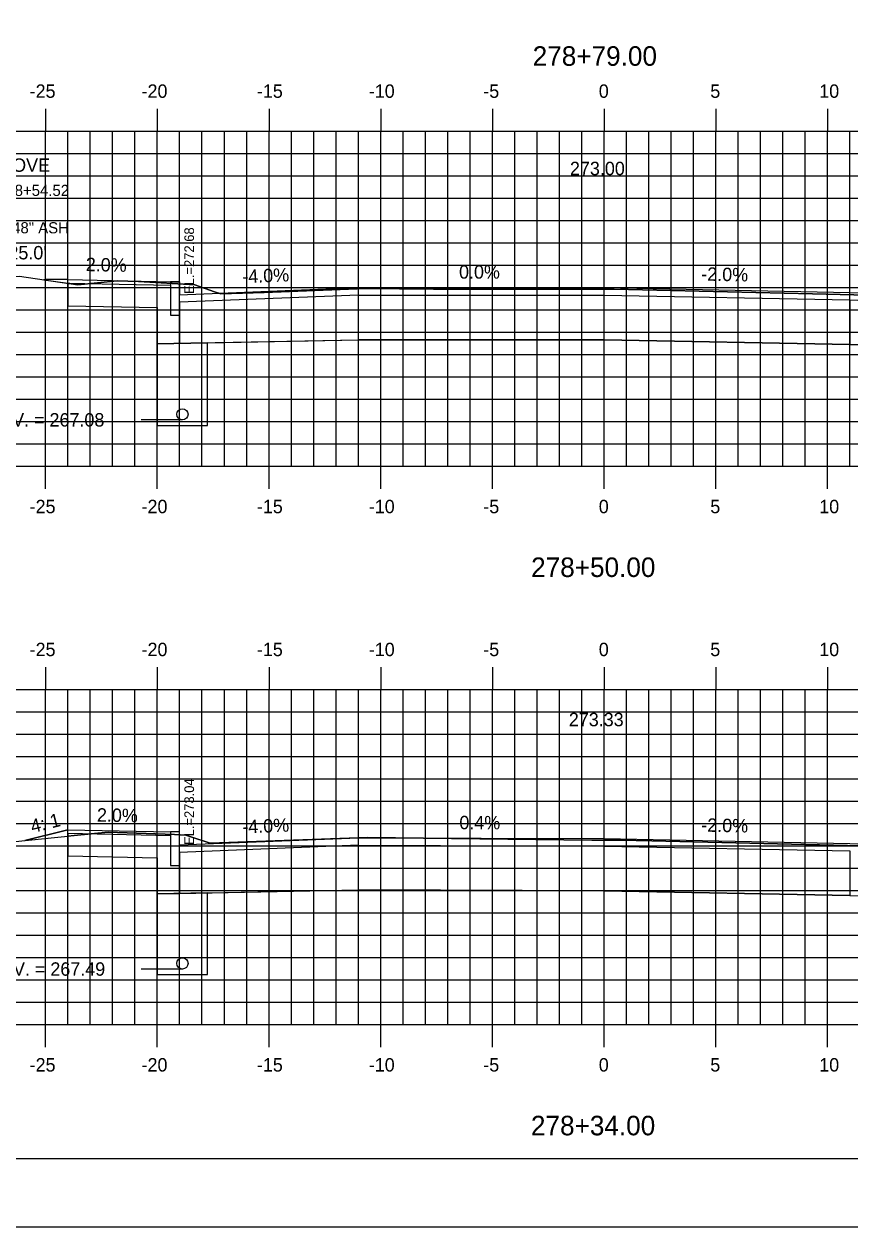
# Model space of a CAD drawing. Extents: x 854676 to 854846, y 366268 to 366378.
# Drawn here: x 854733.1 to 854770.1, y 366268.2 to 366322 of the extents above; entities that cross this region are included whole.
import ezdxf

# ---------------------------------------------------------------- set-up
doc = ezdxf.new("R2010")
doc.units = 0
for name, color, linetype in [('ANNOTATION', 7, 'Continuous'), ('BORDER', 7, 'Continuous'), ('D_Curb_Type_1_Lt', 7, 'Continuous'), ('D_Roadway_Centerline', 7, 'Continuous'), ('D_Roadway_Centerline_Text', 7, 'Continuous'), ('D_Roadway_Edge_Shoulder', 7, 'Continuous'), ('D_Roadway_FinishedGrade', 7, 'Continuous'), ('D_Roadway_Sidewalks_Paved', 7, 'Continuous'), ('D_Roadway_SubGrade', 7, 'Continuous'), ('D_Text_Monospaced', 7, 'Continuous'), ('D_Text_Standard', 7, 'Continuous'), ('H_V ANNOTATION', 7, 'Continuous'), ('JUNK COM EXC', 7, 'Continuous'), ('JUNK FILL', 7, 'Continuous'), ('junk strct exc', 7, 'Continuous'), ('MAJOR', 7, 'Continuous'), ('MINOR', 7, 'Continuous'), ('PDRAIN', 7, 'Continuous'), ('PLOT BOUNDARY', 7, 'Continuous'), ('S_Roadway_Centerline', 7, 'Continuous')]:
    doc.layers.add(name, color=color, linetype=linetype)

msp = doc.modelspace()

# ---------------------------------------------------------------- linework, layer by layer
at = {"layer": 'BORDER'}
msp.add_line((854684.107, 366271.236), (854844.107, 366271.236), dxfattribs=at)
at = {"layer": 'D_Curb_Type_1_Lt'}
for points in [[(854739.69, 366310.503), (854739.69, 366309.003), (854740.106, 366309.003), (854740.106, 366310.503)], [(854739.69, 366285.864), (854739.69, 366284.364), (854740.106, 366284.364), (854740.106, 366285.864)]]:
    msp.add_lwpolyline(points, close=True, dxfattribs=at)
at = {"layer": 'D_Roadway_Centerline'}
for points in [[(854734.024, 366310.589), (854734.101, 366310.615), (854735.101, 366310.595), (854739.69, 366310.503), (854740.101, 366310.503), (854740.106, 366309.92), (854748.106, 366310.24)], [(854748.106, 366310.24), (854759.106, 366310.24), (854770.106, 366310.02)]]:
    msp.add_lwpolyline(points, dxfattribs=at)
at = {"layer": 'D_Roadway_Edge_Shoulder'}
for points in [[(854740.106, 366309.92), (854748.106, 366310.24), (854759.106, 366310.24), (854770.106, 366310.02), (854778.103, 366309.701)], [(854740.106, 366285.281), (854748.106, 366285.601), (854759.106, 366285.566), (854770.106, 366285.346), (854778.107, 366285.025)]]:
    msp.add_lwpolyline(points, dxfattribs=at)
at = {"layer": 'D_Roadway_FinishedGrade'}
msp.add_line((854733.178, 366285.475), (854735.101, 366285.956), dxfattribs=at)
for points in [[(854734.101, 366310.615), (854734.024, 366310.589)], [(854735.101, 366310.595), (854734.101, 366310.615)]]:
    msp.add_lwpolyline(points, dxfattribs=at)
at = {"layer": 'D_Roadway_Sidewalks_Paved'}
for points in [[(854735.101, 366310.595), (854739.69, 366310.503), (854739.69, 366310.337), (854735.101, 366310.429)], [(854735.101, 366285.956), (854739.69, 366285.864), (854739.69, 366285.697), (854735.101, 366285.789)]]:
    msp.add_lwpolyline(points, close=True, dxfattribs=at)
at = {"layer": 'D_Roadway_SubGrade'}
for points in [[(854735.101, 366310.429), (854735.101, 366309.428), (854739.106, 366309.348), (854739.106, 366307.727), (854740.106, 366307.747)], [(854735.101, 366285.789), (854735.101, 366284.789), (854739.106, 366284.709), (854739.106, 366283.087), (854740.106, 366283.107)]]:
    msp.add_lwpolyline(points, dxfattribs=at)
for points in [[(854748.106, 366309.907), (854740.106, 366309.587), (854740.106, 366307.747), (854748.106, 366307.907)], [(854748.106, 366307.907), (854748.106, 366309.907), (854759.106, 366309.907), (854770.106, 366309.687), (854770.106, 366307.687), (854759.106, 366307.907)], [(854770.106, 366309.687), (854778.106, 366309.367), (854778.106, 366307.527), (854770.106, 366307.687)], [(854748.106, 366285.267), (854740.106, 366284.947), (854740.106, 366283.107), (854748.106, 366283.267)], [(854748.106, 366283.267), (854748.106, 366285.267), (854759.106, 366285.232), (854770.106, 366285.012), (854770.106, 366283.012), (854759.106, 366283.232)]]:
    msp.add_lwpolyline(points, close=True, dxfattribs=at)
at = {"layer": 'D_Text_Standard'}
for points in [[(854740.231, 366304.317), (854739.06, 366304.317), (854738.38, 366304.317)], [(854740.231, 366279.726), (854739.061, 366279.726), (854738.381, 366279.726)]]:
    msp.add_lwpolyline(points, dxfattribs=at)
at = {"layer": 'JUNK COM EXC'}
for points in [[(854771.526, 366309.892), (854768.432, 366309.965), (854759.551, 366310.169), (854751.474, 366310.169), (854748.429, 366310.204), (854743.884, 366310.025), (854741.948, 366309.957), (854741.663, 366310.048), (854740.788, 366310.363), (854738.261, 366310.513), (854737.315, 366310.547), (854735.545, 366310.37), (854735.101, 366310.434)], [(854735.101, 366310.434), (854735.101, 366309.428), (854739.106, 366309.348), (854739.106, 366307.727), (854748.106, 366307.907), (854759.106, 366307.907), (854770.106, 366307.687), (854779.106, 366307.507)], [(854735.101, 366285.679), (854735.101, 366284.789), (854739.106, 366284.709), (854739.106, 366283.087), (854748.106, 366283.267), (854759.106, 366283.232), (854770.106, 366283.012), (854779.107, 366282.832), (854779.107, 366284.966), (854773.78, 366285.165), (854773.739, 366285.161), (854771.879, 366285.217), (854761.239, 366285.468), (854759.829, 366285.5), (854758.547, 366285.5), (854748.52, 366285.618), (854747.7, 366285.585), (854741.471, 366285.366), (854740.556, 366285.66), (854740.379, 366285.723), (854739.868, 366285.754), (854736.899, 366285.86), (854735.383, 366285.709), (854735.101, 366285.679)]]:
    msp.add_lwpolyline(points, dxfattribs=at)
at = {"layer": 'JUNK FILL'}
msp.add_lwpolyline([(854735.101, 366310.434), (854735.101, 366310.595), (854734.101, 366310.615), (854734.024, 366310.589), (854735.101, 366310.434)], dxfattribs=at)
msp.add_lwpolyline([(854735.106, 366285.679), (854735.106, 366285.956), (854735.101, 366285.956), (854733.178, 366285.475)], close=True, dxfattribs=at)
at = {"layer": 'junk strct exc'}
for points in [[(854739.106, 366307.727), (854739.106, 366304.066), (854741.356, 366304.066), (854741.356, 366307.772)], [(854739.106, 366283.087), (854739.106, 366279.476), (854741.356, 366279.476), (854741.356, 366283.132)]]:
    msp.add_lwpolyline(points, close=True, dxfattribs=at)
at = {"layer": 'MAJOR'}
for p, q in [((854734.106, 366318.238), (854734.106, 366317.236)), ((854739.106, 366318.238), (854739.106, 366317.236)), ((854744.106, 366318.238), (854744.106, 366317.236)), ((854749.106, 366318.238), (854749.106, 366317.236)), ((854754.106, 366318.238), (854754.106, 366317.236)), ((854759.106, 366318.238), (854759.106, 366317.236)), ((854764.106, 366318.238), (854764.106, 366317.236)), ((854769.106, 366318.238), (854769.106, 366317.236)), ((854689.106, 366317.236), (854829.106, 366317.236)), ((854689.106, 366317.236), (854829.106, 366317.236)), ((854734.106, 366302.236), (854734.106, 366317.236)), ((854739.106, 366302.236), (854739.106, 366317.236)), ((854744.106, 366302.236), (854744.106, 366317.236)), ((854749.106, 366302.236), (854749.106, 366317.236)), ((854754.106, 366302.236), (854754.106, 366317.236)), ((854759.106, 366302.236), (854759.106, 366317.236)), ((854764.106, 366302.236), (854764.106, 366317.236)), ((854769.106, 366302.236), (854769.106, 366317.236)), ((854689.106, 366312.236), (854829.106, 366312.236)), ((854689.106, 366307.236), (854829.106, 366307.236)), ((854689.106, 366302.236), (854829.106, 366302.236)), ((854689.106, 366302.236), (854829.106, 366302.236)), ((854734.106, 366301.234), (854734.106, 366302.236)), ((854739.106, 366301.234), (854739.106, 366302.236)), ((854744.106, 366301.234), (854744.106, 366302.236)), ((854749.106, 366301.234), (854749.106, 366302.236)), ((854754.106, 366301.234), (854754.106, 366302.236)), ((854759.106, 366301.234), (854759.106, 366302.236)), ((854764.106, 366301.234), (854764.106, 366302.236)), ((854769.106, 366301.234), (854769.106, 366302.236)), ((854734.106, 366293.238), (854734.106, 366292.236)), ((854739.106, 366293.238), (854739.106, 366292.236)), ((854744.106, 366293.238), (854744.106, 366292.236)), ((854749.106, 366293.238), (854749.106, 366292.236)), ((854754.106, 366293.238), (854754.106, 366292.236)), ((854759.106, 366293.238), (854759.106, 366292.236)), ((854764.106, 366293.238), (854764.106, 366292.236)), ((854769.106, 366293.238), (854769.106, 366292.236)), ((854689.106, 366292.236), (854829.106, 366292.236)), ((854689.106, 366292.236), (854829.106, 366292.236)), ((854734.106, 366277.236), (854734.106, 366292.236)), ((854739.106, 366277.236), (854739.106, 366292.236)), ((854744.106, 366277.236), (854744.106, 366292.236)), ((854749.106, 366277.236), (854749.106, 366292.236)), ((854754.106, 366277.236), (854754.106, 366292.236)), ((854759.106, 366277.236), (854759.106, 366292.236)), ((854764.106, 366277.236), (854764.106, 366292.236)), ((854769.106, 366277.236), (854769.106, 366292.236)), ((854689.106, 366287.236), (854829.106, 366287.236)), ((854689.106, 366282.236), (854829.106, 366282.236)), ((854689.106, 366277.236), (854829.106, 366277.236)), ((854689.106, 366277.236), (854829.106, 366277.236)), ((854734.106, 366276.234), (854734.106, 366277.236)), ((854739.106, 366276.234), (854739.106, 366277.236)), ((854744.106, 366276.234), (854744.106, 366277.236)), ((854749.106, 366276.234), (854749.106, 366277.236)), ((854754.106, 366276.234), (854754.106, 366277.236)), ((854759.106, 366276.234), (854759.106, 366277.236)), ((854764.106, 366276.234), (854764.106, 366277.236)), ((854769.106, 366276.234), (854769.106, 366277.236))]:
    msp.add_line(p, q, dxfattribs=at)
at = {"layer": 'MINOR'}
for p, q in [((854735.106, 366302.236), (854735.106, 366317.236)), ((854736.106, 366302.236), (854736.106, 366317.236)), ((854737.106, 366302.236), (854737.106, 366317.236)), ((854738.106, 366302.236), (854738.106, 366317.236)), ((854740.106, 366302.236), (854740.106, 366317.236)), ((854741.106, 366302.236), (854741.106, 366317.236)), ((854742.106, 366302.236), (854742.106, 366317.236)), ((854743.106, 366302.236), (854743.106, 366317.236)), ((854745.106, 366302.236), (854745.106, 366317.236)), ((854746.106, 366302.236), (854746.106, 366317.236)), ((854747.106, 366302.236), (854747.106, 366317.236)), ((854748.106, 366302.236), (854748.106, 366317.236)), ((854750.106, 366302.236), (854750.106, 366317.236)), ((854751.106, 366302.236), (854751.106, 366317.236)), ((854752.106, 366302.236), (854752.106, 366317.236)), ((854753.106, 366302.236), (854753.106, 366317.236)), ((854755.106, 366302.236), (854755.106, 366317.236)), ((854756.106, 366302.236), (854756.106, 366317.236)), ((854757.106, 366302.236), (854757.106, 366317.236)), ((854758.106, 366302.236), (854758.106, 366317.236)), ((854760.106, 366302.236), (854760.106, 366317.236)), ((854761.106, 366302.236), (854761.106, 366317.236)), ((854762.106, 366302.236), (854762.106, 366317.236)), ((854763.106, 366302.236), (854763.106, 366317.236)), ((854765.106, 366302.236), (854765.106, 366317.236)), ((854766.106, 366302.236), (854766.106, 366317.236)), ((854767.106, 366302.236), (854767.106, 366317.236)), ((854768.106, 366302.236), (854768.106, 366317.236)), ((854770.106, 366302.236), (854770.106, 366317.236)), ((854689.106, 366316.236), (854829.106, 366316.236)), ((854689.106, 366315.236), (854829.106, 366315.236)), ((854689.106, 366314.236), (854829.106, 366314.236)), ((854689.106, 366313.236), (854829.106, 366313.236)), ((854689.106, 366311.236), (854829.106, 366311.236)), ((854689.106, 366310.236), (854829.106, 366310.236)), ((854689.106, 366309.236), (854829.106, 366309.236)), ((854689.106, 366308.236), (854829.106, 366308.236)), ((854689.106, 366306.236), (854829.106, 366306.236)), ((854689.106, 366305.236), (854829.106, 366305.236)), ((854689.106, 366304.236), (854829.106, 366304.236)), ((854689.106, 366303.236), (854829.106, 366303.236)), ((854735.106, 366277.236), (854735.106, 366292.236)), ((854736.106, 366277.236), (854736.106, 366292.236)), ((854737.106, 366277.236), (854737.106, 366292.236)), ((854738.106, 366277.236), (854738.106, 366292.236)), ((854740.106, 366277.236), (854740.106, 366292.236)), ((854741.106, 366277.236), (854741.106, 366292.236)), ((854742.106, 366277.236), (854742.106, 366292.236)), ((854743.106, 366277.236), (854743.106, 366292.236)), ((854745.106, 366277.236), (854745.106, 366292.236)), ((854746.106, 366277.236), (854746.106, 366292.236)), ((854747.106, 366277.236), (854747.106, 366292.236)), ((854748.106, 366277.236), (854748.106, 366292.236)), ((854750.106, 366277.236), (854750.106, 366292.236)), ((854751.106, 366277.236), (854751.106, 366292.236)), ((854752.106, 366277.236), (854752.106, 366292.236)), ((854753.106, 366277.236), (854753.106, 366292.236)), ((854755.106, 366277.236), (854755.106, 366292.236)), ((854756.106, 366277.236), (854756.106, 366292.236)), ((854757.106, 366277.236), (854757.106, 366292.236)), ((854758.106, 366277.236), (854758.106, 366292.236)), ((854760.106, 366277.236), (854760.106, 366292.236)), ((854761.106, 366277.236), (854761.106, 366292.236)), ((854762.106, 366277.236), (854762.106, 366292.236)), ((854763.106, 366277.236), (854763.106, 366292.236)), ((854765.106, 366277.236), (854765.106, 366292.236)), ((854766.106, 366277.236), (854766.106, 366292.236)), ((854767.106, 366277.236), (854767.106, 366292.236)), ((854768.106, 366277.236), (854768.106, 366292.236)), ((854689.106, 366291.236), (854829.106, 366291.236)), ((854689.106, 366290.236), (854829.106, 366290.236)), ((854689.106, 366289.236), (854829.106, 366289.236)), ((854689.106, 366288.236), (854829.106, 366288.236)), ((854689.106, 366286.236), (854829.106, 366286.236)), ((854689.106, 366285.236), (854829.106, 366285.236)), ((854689.106, 366284.236), (854829.106, 366284.236)), ((854689.106, 366283.236), (854829.106, 366283.236)), ((854689.106, 366281.236), (854829.106, 366281.236)), ((854689.106, 366280.236), (854829.106, 366280.236)), ((854689.106, 366279.236), (854829.106, 366279.236)), ((854689.106, 366278.236), (854829.106, 366278.236))]:
    msp.add_line(p, q, dxfattribs=at)
at = {"layer": 'PDRAIN'}
for points in [[(854739.106, 366307.727), (854739.106, 366304.066), (854741.356, 366304.066), (854741.356, 366307.772)], [(854739.106, 366283.087), (854739.106, 366279.476), (854741.356, 366279.476), (854741.356, 366283.132)]]:
    msp.add_lwpolyline(points, dxfattribs=at)
for centre in [(854740.231, 366304.566), (854740.231, 366279.976)]:
    msp.add_circle(centre, 0.25, dxfattribs=at)
at = {"layer": 'PLOT BOUNDARY'}
msp.add_lwpolyline([(854676.013, 366268.177), (854846.013, 366268.177), (854846.013, 366378.177), (854676.013, 366378.177)], close=True, dxfattribs=at)
at = {"layer": 'S_Roadway_Centerline'}
for points in [[(854702.478, 366309.069), (854721.133, 366310.121), (854725.449, 366310.212), (854732.94, 366310.746), (854735.545, 366310.37), (854737.315, 366310.547), (854738.261, 366310.513), (854740.788, 366310.363), (854741.663, 366310.048), (854741.948, 366309.957), (854743.884, 366310.025), (854748.429, 366310.204), (854751.474, 366310.169), (854759.551, 366310.169), (854768.432, 366309.965), (854771.526, 366309.892)], [(854700.471, 366284.322), (854708.905, 366284.797), (854721.694, 366285.065), (854732.614, 366285.415), (854735.383, 366285.709), (854736.899, 366285.86), (854739.868, 366285.754), (854740.379, 366285.723), (854740.556, 366285.66), (854741.471, 366285.366), (854747.7, 366285.585), (854748.52, 366285.618), (854758.547, 366285.5), (854759.829, 366285.5), (854761.239, 366285.468), (854771.879, 366285.217)]]:
    msp.add_lwpolyline(points, dxfattribs=at)

# ---------------------------------------------------------------- texts
at = {"layer": 'ANNOTATION'}
msp.add_text('REMOVE', height=0.6, dxfattribs=at).set_placement((854730.827, 366315.423))
for s, rotation, p in [('2.0%', 358.8542, (854735.899, 366310.979)), ('-4.0%', 2.2906, (854742.922, 366310.434)), ('0.0%', 360, (854752.611, 366310.64)), ('-2.0%', 358.8542, (854763.449, 366310.553)), ('2.0%', 358.8542, (854736.399, 366286.33)), ('4: 1', 14.0362, (854733.517, 366285.811)), ('-4.0%', 2.2906, (854742.922, 366285.794)), ('0.4%', 359.8167, (854752.625, 366285.986)), ('-2.0%', 358.8542, (854763.449, 366285.879))]:
    msp.add_text(s, height=0.6, rotation=rotation, dxfattribs=at).set_placement(p)
at = {"layer": 'D_Roadway_Centerline_Text'}
for s, p in [('273.00', (854757.576, 366315.272)), ('273.33', (854757.525, 366290.598))]:
    msp.add_text(s, height=0.6, dxfattribs=at).set_placement(p)
at = {"layer": 'D_Text_Monospaced'}
for s, p in [('STA. 278+54.52', (854730.306, 366314.342)), ('EXIST. 48" ASH', (854730.306, 366312.668))]:
    msp.add_text(s, height=0.49998, dxfattribs=at).set_placement(p)
at = {"layer": 'D_Text_Standard'}
for s, p in [(' EL.=272.68', (854740.75, 366309.794)), (' EL.=273.04', (854740.75, 366285.12))]:
    msp.add_text(s, height=0.4335, rotation=90, dxfattribs=at).set_placement(p)
for s, p in [("-25.0'", (854732.174, 366311.502)), ('ELEV. = 267.08', (854731.092, 366304.017)), ('ELEV. = 267.49', (854731.13, 366279.426))]:
    msp.add_text(s, height=0.6, dxfattribs=at).set_placement(p)
at = {"layer": 'H_V ANNOTATION'}
for s, height, p in [('278+79.00', 0.875, (854755.907, 366320.171)), ('-25', 0.6, (854733.392, 366318.736)), ('-20', 0.6, (854738.4, 366318.736)), ('-15', 0.6, (854743.563, 366318.736)), ('-10', 0.6, (854748.571, 366318.736)), ('-5', 0.6, (854753.697, 366318.736)), ('0', 0.6, (854758.865, 366318.736)), ('5', 0.6, (854763.857, 366318.736)), ('10', 0.6, (854768.732, 366318.736)), ('-25', 0.6, (854733.392, 366300.136)), ('-20', 0.6, (854738.4, 366300.136)), ('-15', 0.6, (854743.563, 366300.136)), ('-10', 0.6, (854748.571, 366300.136)), ('-5', 0.6, (854753.697, 366300.136)), ('0', 0.6, (854758.865, 366300.136)), ('5', 0.6, (854763.857, 366300.136)), ('10', 0.6, (854768.732, 366300.136)), ('278+50.00', 0.875, (854755.837, 366297.28)), ('-25', 0.6, (854733.392, 366293.736)), ('-20', 0.6, (854738.4, 366293.736)), ('-10', 0.6, (854748.571, 366293.736)), ('0', 0.6, (854758.865, 366293.736)), ('10', 0.6, (854768.732, 366293.736)), ('-15', 0.6, (854743.563, 366293.736)), ('-5', 0.6, (854753.697, 366293.736)), ('5', 0.6, (854763.857, 366293.736)), ('-25', 0.6, (854733.392, 366275.136)), ('-20', 0.6, (854738.4, 366275.136)), ('-15', 0.6, (854743.563, 366275.136)), ('-10', 0.6, (854748.571, 366275.136)), ('-5', 0.6, (854753.697, 366275.136)), ('0', 0.6, (854758.865, 366275.136)), ('5', 0.6, (854763.857, 366275.136)), ('10', 0.6, (854768.732, 366275.136)), ('278+34.00', 0.875, (854755.829, 366272.28))]:
    msp.add_text(s, height=height, dxfattribs=at).set_placement(p)
at = {"layer": 'S_Roadway_Centerline'}
for s, p in [('C', (854759.546, 366310.169)), ('L', (854759.551, 366310.161)), ('C', (854759.824, 366285.5)), ('L', (854759.829, 366285.493))]:
    msp.add_text(s, height=0.0146, dxfattribs=at).set_placement(p)

doc.saveas('drawing.dxf')
